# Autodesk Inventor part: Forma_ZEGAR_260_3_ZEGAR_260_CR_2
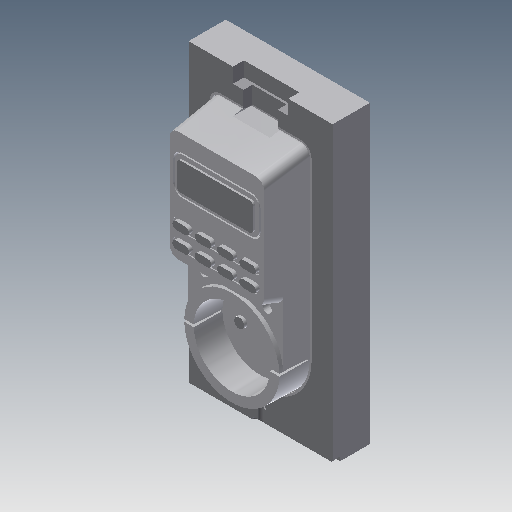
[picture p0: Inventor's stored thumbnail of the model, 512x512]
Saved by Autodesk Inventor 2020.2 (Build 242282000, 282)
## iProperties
Created: 2015-01
Part Number: Forma_ZEGAR_260_3_ZEGAR_260_CR_2
Material: Ogólny
Document SubType Name: Modeling
Designer: F.Stasiak
Density: 1 g/cm^3
Appearance: Domyślna
Catalog Web Link: www.expertbooks.pl
Manager: www.cadconsulting.pl
Company: Fabian Stasiak CAD Consulting
Author: F.Stasiak
Subject: Zbiór ćwiczeń. Autodesk Inventor 2020. Kurs Professional
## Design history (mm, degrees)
node "Forma_ZEGAR_260_3_ZEGAR_260_CR_Base"
feature "Rzeźbienie3"
feature "Bryła1::Forma_ZEGAR_260_3_ZEGAR_260_CR_Base"
tag "Bryła wyprowadzona1"
node "Bryła1"
feature "Forma_ZEGAR_260_3_ZEGAR_260_CR_Base_Bodies"
feature "Powierzchnia3"
body "Srf3"
